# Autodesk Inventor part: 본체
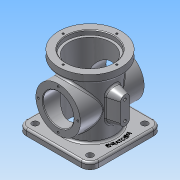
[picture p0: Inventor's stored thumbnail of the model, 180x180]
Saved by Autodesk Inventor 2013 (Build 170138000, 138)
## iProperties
Created: 2021-03
Part Number: 본체
Material: 알루미늄 6061
Document SubType Name: Modeling
Designer: Administrator
Density: 2.71 g/cm^3
Mass: 833.809 g
Surface Area: 863.886 cm^2
Volume: 307.678 cm^3
Author: Administrator
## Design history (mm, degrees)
sketch "스케치1"
  geometry: L1 (57, -57)-(-57, -57); L2 (-57, -57)-(-57, 57); L3 (-57, 57)-(57, 57); L4 (57, 57)-(57, -57); L5 (57, -57)-(-57, 57); L6 (-57, -57)-(57, 57); C1 r 38 at (0, 0); 1 further point
  constraints: 12 end point, 3 midpoint, 2 parallel, 2 perpendicular, 1 centre point, 1 horizontal
  dimensions: "d0" = 114 distance of L2.end L3.end; "d4" = 76 diameter of C1
extrude "돌출1" new body sketch "스케치1" distance "d2" = 10; taper "d3" = 0 deg
extrude "돌출2" join sketch "스케치1" distance "d5" = 98; taper "d6" = 0 deg
sketch "스케치2"
  geometry: C1 r 49 at (0, 0); 1 further point
  constraints: 1 centre point, 1 coincident
  dimensions: "d7" = 98 diameter of C1
extrude "돌출3" join sketch "스케치2" distance "d9" = 13; taper "d10" = 0 deg
sketch "스케치3"
  geometry: C1 r 35 at (0, 54); 1 further point
  constraints: 1 centre point, 1 vertical alignment
  dimensions: "d20" = 70 diameter of C1; "d22" = 54 distance of point (0, 0) C1.centre
extrude "돌출4" join sketch "스케치3" stored distance "d24" = 100; taper "d25" = 0 deg
hole "구멍2" diameter "d28" = 66; stored, may be unused: countersink angle "d32" = 90 deg, drill point angle "d34" = 0 deg; dims "d26" = 10, "d27" = 10, "d29" = 6, "d30" = 74, "d31" = 7, "d33" = 111
hole "구멍3" diameter "d37" = 48; stored, may be unused: countersink angle "d41" = 90 deg, drill point angle "d43" = 0 deg; dims "d35" = 10, "d36" = 10, "d38" = 6, "d39" = 74, "d40" = 7, "d42" = 111
sketch "스케치4"
  geometry: 2 further points
  constraints: 1 vertical alignment
  dimensions: "d44" = 42 distance of point (0, 42) point (0, 0)
hole "구멍4" sketch "스케치4" at (0, 42) diameter "d45" = 3.242; stored, may be unused: countersink angle "d49" = 90 deg, drill point angle "d51" = 118 deg; dims "d46" = 6, "d47" = 74, "d48" = 7, "d50" = 8
sketch "스케치5"
  geometry: L1 (54, 57)-(54, -57) reference; C1 r 24 at (0, 0) reference; 3 further points
  constraints: 1 horizontal alignment, 1 midpoint
  dimensions: "d55" = 31 distance of point (-31, 0) C1.centre
hole "구멍5" sketch "스케치5" at (-31, 0) diameter "d56" = 3.242; stored, may be unused: countersink angle "d60" = 90 deg, drill point angle "d62" = 118 deg; dims "d57" = 6, "d58" = 74, "d59" = 7, "d61" = 8
node "작업 평면1"
sketch "스케치6"
  geometry: L1 (7, 41)-(7, 70); L2 (-7, 70)-(-7, 41); L3 (50, 19)-(50, 89) reference; L4 (57, 0)-(-57, 0) reference; A1 r 7 centre (0, 70) between (7, 70) and (-7, 70); A2 r 7 centre (0, 41) between (-7, 41) and (7, 41); 3 further points
  constraints: 4 end point, 4 point on circle, 4 tangent, 2 centre point, 2 midpoint, 2 vertical alignment, 1 parallel, 1 vertical
  dimensions: "d67" = 43 dimension on A2 A1; "d69" = 7 radius of A1; "d114" = 13 vertical distance of point (50, 54) A2.centre
extrude "돌출5" join sketch "스케치6" stored distance "d70" = 100; taper "d71" = 15 deg
fillet "모깎기1" dims "d72" = 14
hole "구멍6" diameter "d75" = 10; stored, may be unused: countersink angle "d79" = 90 deg, drill point angle "d81" = 0 deg; dims "d73" = 10, "d74" = 10, "d76" = 6, "d77" = 74, "d78" = 7, "d80" = 8
fillet "모깎기2" dims "d88" = 3
chamfer "모따기1" distance "d89" = 1; stored, may be unused: second distance "d90" = 2, angle "d91" = 45 deg
hole "구멍7" diameter "d94" = 4.134; stored, may be unused: countersink angle "d98" = 90 deg, drill point angle "d100" = 118 deg; dims "d92" = 10, "d93" = 10, "d95" = 8, "d96" = 74, "d97" = 7, "d99" = 10
hole "구멍8" diameter "d103" = 4.134; stored, may be unused: countersink angle "d107" = 90 deg, drill point angle "d109" = 118 deg; dims "d101" = 10, "d102" = 10, "d104" = 8, "d105" = 74, "d106" = 7, "d108" = 10
sketch "스케치7"
  geometry: C1 r 50 at (0, 0); 1 further point
  constraints: 1 centre point, 1 coincident, 1 other
  dimensions: "d110" = 100 diameter of C1
feature "엠보싱1" sketch "스케치7" dims "d0" = 114, "d4" = 76, "d112" = 0.5, "d113" = 0
node "솔리드1"
pattern_circular "원형 패턴1" dims angle "d53" = 360 deg
pattern_circular "원형 패턴2" dims angle "d64" = 360 deg
mirror "대칭1"
pattern_linear "직사각형 패턴1" dims "d84" = 86, "d87" = 86
other parameters: "d66" = 55
